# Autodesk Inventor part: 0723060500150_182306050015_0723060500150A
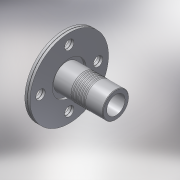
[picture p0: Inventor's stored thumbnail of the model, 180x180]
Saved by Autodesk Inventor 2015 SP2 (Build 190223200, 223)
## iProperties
Created: 2017-02
Part Number: 0723060500150_182306050015_0723060500150A
Material: PVC-Piping
Description: PLASSON FLANGE ADAPTOR WITH METAL FLANGE 50-1.1/2"
Document SubType Name: Modeling
Designer: KIM
Mass: 92.6774 g
Surface Area: 199.44 cm^2
Volume: 66.1981 cm^3
Density: 1.4 g/cm^3
Appearance: Smooth - White
Author: KIM
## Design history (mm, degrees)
derived "072306.ipt"
feature "Solid1::072306.ipt"
tag "TaggingFeature1"
body "Solid1"
other parameters: "d73" = 9.9, "d74" = 90 deg, "d75" = 0.3, "d77" = 18, "d78" = 55, "d80" = 0, "d82" = 360 deg, "d96" = 0.3, "d99" = 360 deg, "d102" = 35, "d103" = 99, "d104" = 1, "d107" = 65, "d108" = 2.475, "d109" = 49, "d110" = 39.6, "d111" = 5, "d115" = 5, "E_" = 82, "H_" = 99, "S_" = 18
